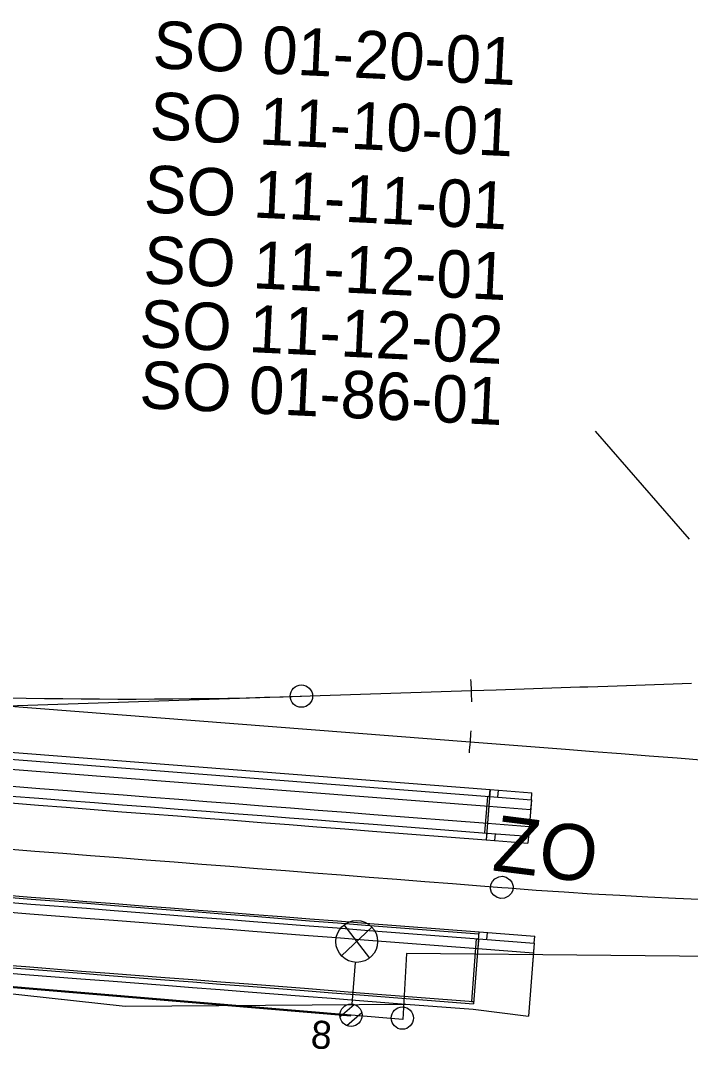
# Model space of a CAD drawing. Extents: x -669628 to -669207, y -977198 to -977075.
# Drawn here: x -669457.17 to -669433.19, y -977154.05 to -977117.21 of the extents above; entities that cross this region are included whole.
import ezdxf

# ---------------------------------------------------------------- set-up
doc = ezdxf.new("R2010")
doc.units = 0
for name, color, linetype in [('_PS_SO_číslo', 7, 'Continuous'), ('SO 01-86-01', 7, 'Continuous'), ('SO 11-10-01', 7, 'Continuous'), ('SO 11-12-01', 7, 'Continuous')]:
    doc.layers.add(name, color=color, linetype=linetype)

# ---------------------------------------------------------------- blocks, each defined once
blk = doc.blocks.new('POINT_DISPLAY')
blk.add_line((0, 0), (0, 0))

msp = doc.modelspace()

# ---------------------------------------------------------------- linework, layer by layer
at = {"layer": '_PS_SO_číslo'}
msp.add_line((-669436.601, -977131.919), (-669433.231, -977135.786), dxfattribs=at)
at = {"layer": 'SO 01-86-01'}
for p, q in [((-669445.341, -977152.857), (-669517.763, -977146.78)), ((-669445.341, -977152.857), (-669517.763, -977146.78)), ((-669443.485, -977152.976), (-669517.763, -977146.78)), ((-669445.675, -977150.701), (-669444.59, -977149.67)), ((-669445.589, -977149.592), (-669444.676, -977150.779)), ((-669443.348, -977150.615), (-669443.485, -977152.976)), ((-669436.037, -977150.686), (-669443.348, -977150.615)), ((-669421.416, -977150.84), (-669436.037, -977150.686)), ((-669445.191, -977150.932), (-669445.307, -977152.427)), ((-669445.732, -977152.875), (-669445.228, -977152.444)), ((-669445.488, -977153.192), (-669444.951, -977152.733))]:
    msp.add_line(p, q, dxfattribs=at)
for centre, radius in [((-669445.133, -977150.185), 0.749), ((-669445.338, -977152.826), 0.4), ((-669443.501, -977152.927), 0.4)]:
    msp.add_circle(centre, radius, dxfattribs=at)
at = {"layer": 'SO 11-10-01'}
for p, q in [((-669468.123, -977140.931), (-669441.067, -977143.037)), ((-669457.632, -977141.747), (-669441.026, -977141.2)), ((-669441.026, -977141.2), (-669440.143, -977141.171)), ((-669440.143, -977141.171), (-669439.143, -977141.138)), ((-669439.143, -977141.138), (-669438.144, -977141.105)), ((-669438.144, -977141.105), (-669437.144, -977141.072)), ((-669437.144, -977141.072), (-669436.855, -977141.062)), ((-669436.855, -977141.062), (-669436.145, -977141.039)), ((-669436.145, -977141.039), (-669435.146, -977141.006)), ((-669435.146, -977141.006), (-669434.146, -977140.973)), ((-669434.146, -977140.973), (-669433.147, -977140.94)), ((-669441.067, -977143.037), (-669437.657, -977143.302)), ((-669437.657, -977143.302), (-669436.66, -977143.38)), ((-669436.66, -977143.38), (-669435.663, -977143.457)), ((-669435.663, -977143.457), (-669434.666, -977143.535)), ((-669434.666, -977143.535), (-669433.669, -977143.613)), ((-669433.669, -977143.613), (-669432.672, -977143.69)), ((-669457.653, -977146.871), (-669456.656, -977146.949)), ((-669456.656, -977146.949), (-669455.659, -977147.026)), ((-669455.659, -977147.026), (-669454.662, -977147.104)), ((-669454.662, -977147.104), (-669453.665, -977147.182)), ((-669453.665, -977147.182), (-669452.668, -977147.259)), ((-669452.668, -977147.259), (-669451.671, -977147.337)), ((-669451.671, -977147.337), (-669450.674, -977147.414)), ((-669450.674, -977147.414), (-669449.677, -977147.492)), ((-669449.677, -977147.492), (-669448.68, -977147.57)), ((-669448.68, -977147.57), (-669447.683, -977147.647)), ((-669447.683, -977147.647), (-669446.686, -977147.725)), ((-669446.686, -977147.725), (-669445.689, -977147.802)), ((-669445.689, -977147.802), (-669444.692, -977147.88)), ((-669444.692, -977147.88), (-669443.695, -977147.958)), ((-669443.695, -977147.958), (-669442.698, -977148.035)), ((-669442.698, -977148.035), (-669441.701, -977148.113)), ((-669441.701, -977148.113), (-669440.704, -977148.191)), ((-669440.704, -977148.191), (-669439.942, -977148.25)), ((-669439.942, -977148.25), (-669439.707, -977148.268)), ((-669439.707, -977148.268), (-669438.71, -977148.342)), ((-669438.71, -977148.342), (-669437.712, -977148.41)), ((-669437.712, -977148.41), (-669436.714, -977148.473)), ((-669436.714, -977148.473), (-669435.716, -977148.531)), ((-669435.716, -977148.531), (-669434.717, -977148.584)), ((-669434.717, -977148.584), (-669433.718, -977148.632)), ((-669433.718, -977148.632), (-669432.879, -977148.667))]:
    msp.add_line(p, q, dxfattribs=at)
msp.add_lwpolyline([(-669439.973, -977148.649), (-669440.104, -977148.612), (-669440.231, -977148.522), (-669440.305, -977148.436), (-669440.347, -977148.299), (-669440.335, -977148.139), (-669440.274, -977148.037), (-669440.186, -977147.937), (-669440.046, -977147.867), (-669439.911, -977147.851), (-669439.781, -977147.888), (-669439.654, -977147.978), (-669439.58, -977148.064), (-669439.537, -977148.201), (-669439.55, -977148.361), (-669439.611, -977148.463), (-669439.699, -977148.563), (-669439.838, -977148.632), (-669439.973, -977148.649)], dxfattribs=at)
msp.add_circle((-669447.114, -977141.4), 0.4, dxfattribs=at)
for centre, radius, start, end in [((-669457.632, -977141.747), 16.616, 0.5101, 3.2688), ((-669453.379, -976951.504), 190, 265.54926, 271.88929), ((-669457.632, -977141.747), 16.616, 354.1699, 356.9286)]:
    msp.add_arc(centre, radius, start, end, dxfattribs=at)
at = {"layer": 'SO 11-12-01'}
for p, q in [((-669470.705, -977142.635), (-669440.379, -977144.996)), ((-669470.686, -977142.386), (-669440.359, -977144.747)), ((-669470.732, -977142.984), (-669440.406, -977145.345)), ((-669457.478, -977144.628), (-669456.481, -977144.706)), ((-669456.481, -977144.706), (-669455.484, -977144.783)), ((-669455.484, -977144.783), (-669454.487, -977144.861)), ((-669454.487, -977144.861), (-669453.49, -977144.938)), ((-669440.359, -977144.747), (-669440.5, -977146.551)), ((-669440.379, -977144.996), (-669440.359, -977144.747)), ((-669440.359, -977144.747), (-669438.864, -977144.863)), ((-669440.079, -977145.019), (-669440.06, -977144.77)), ((-669438.883, -977145.113), (-669438.864, -977144.863)), ((-669457.525, -977145.226), (-669456.528, -977145.304)), ((-669457.505, -977144.977), (-669456.508, -977145.055)), ((-669456.508, -977145.055), (-669455.511, -977145.132)), ((-669455.511, -977145.132), (-669454.514, -977145.21)), ((-669454.514, -977145.21), (-669453.517, -977145.287)), ((-669453.517, -977145.287), (-669452.52, -977145.365)), ((-669453.49, -977144.938), (-669452.493, -977145.016)), ((-669452.493, -977145.016), (-669451.496, -977145.094)), ((-669451.496, -977145.094), (-669450.499, -977145.171)), ((-669450.499, -977145.171), (-669449.502, -977145.249)), ((-669449.502, -977145.249), (-669448.505, -977145.326)), ((-669440.458, -977144.99), (-669440.56, -977146.296)), ((-669440.382, -977145.046), (-669440.437, -977145.744)), ((-669440.379, -977144.996), (-669438.883, -977145.113)), ((-669438.883, -977145.113), (-669438.985, -977146.419)), ((-669438.883, -977145.113), (-669438.91, -977145.461)), ((-669456.528, -977145.304), (-669455.531, -977145.381)), ((-669455.531, -977145.381), (-669454.534, -977145.459)), ((-669454.534, -977145.459), (-669453.537, -977145.537)), ((-669453.537, -977145.537), (-669452.54, -977145.614)), ((-669452.54, -977145.614), (-669451.543, -977145.692)), ((-669452.52, -977145.365), (-669451.523, -977145.443)), ((-669451.523, -977145.443), (-669450.526, -977145.52)), ((-669450.526, -977145.52), (-669449.529, -977145.598)), ((-669449.529, -977145.598), (-669448.532, -977145.675)), ((-669448.505, -977145.326), (-669447.508, -977145.404)), ((-669447.508, -977145.404), (-669446.511, -977145.482)), ((-669446.511, -977145.482), (-669445.514, -977145.559)), ((-669445.514, -977145.559), (-669444.517, -977145.637)), ((-669444.517, -977145.637), (-669440.453, -977145.953)), ((-669440.406, -977145.345), (-669438.91, -977145.461)), ((-669451.543, -977145.692), (-669450.546, -977145.769)), ((-669450.546, -977145.769), (-669449.549, -977145.847)), ((-669449.549, -977145.847), (-669448.552, -977145.925)), ((-669448.552, -977145.925), (-669447.555, -977146.002)), ((-669448.532, -977145.675), (-669447.535, -977145.753)), ((-669447.555, -977146.002), (-669446.558, -977146.08)), ((-669447.535, -977145.753), (-669446.538, -977145.831)), ((-669446.538, -977145.831), (-669445.541, -977145.908)), ((-669445.541, -977145.908), (-669444.544, -977145.986)), ((-669444.544, -977145.986), (-669440.48, -977146.302)), ((-669440.454, -977145.953), (-669438.957, -977146.066)), ((-669446.558, -977146.08), (-669445.561, -977146.157)), ((-669445.561, -977146.157), (-669444.564, -977146.235)), ((-669444.564, -977146.235), (-669440.5, -977146.551)), ((-669440.481, -977146.302), (-669440.5, -977146.551)), ((-669440.481, -977146.302), (-669438.985, -977146.415)), ((-669440.182, -977146.325), (-669440.2, -977146.574)), ((-669438.985, -977146.415), (-669438.959, -977146.066)), ((-669440.5, -977146.551), (-669439.004, -977146.664)), ((-669438.985, -977146.415), (-669439.004, -977146.664)), ((-669457.786, -977148.586), (-669456.789, -977148.664)), ((-669457.781, -977148.516), (-669456.784, -977148.594)), ((-669456.784, -977148.594), (-669455.787, -977148.671)), ((-669457.8, -977148.765), (-669456.803, -977148.843)), ((-669456.803, -977148.843), (-669454.809, -977148.998)), ((-669456.789, -977148.664), (-669454.795, -977148.819)), ((-669455.787, -977148.671), (-669454.79, -977148.749)), ((-669454.795, -977148.819), (-669453.798, -977148.896)), ((-669454.79, -977148.749), (-669453.793, -977148.827)), ((-669453.798, -977148.896), (-669451.804, -977149.052)), ((-669453.793, -977148.827), (-669452.796, -977148.904)), ((-669452.796, -977148.904), (-669451.799, -977148.982)), ((-669457.827, -977149.114), (-669456.83, -977149.192)), ((-669456.83, -977149.192), (-669454.836, -977149.347)), ((-669454.809, -977148.998), (-669453.812, -977149.076)), ((-669453.812, -977149.076), (-669451.818, -977149.231)), ((-669451.818, -977149.231), (-669450.821, -977149.309)), ((-669451.804, -977149.052), (-669450.807, -977149.129)), ((-669451.799, -977148.982), (-669450.802, -977149.059)), ((-669450.821, -977149.309), (-669449.824, -977149.386)), ((-669450.807, -977149.129), (-669449.81, -977149.207)), ((-669450.802, -977149.059), (-669449.805, -977149.137)), ((-669449.81, -977149.207), (-669448.813, -977149.284)), ((-669449.805, -977149.137), (-669448.808, -977149.215)), ((-669448.813, -977149.284), (-669446.819, -977149.44)), ((-669448.808, -977149.215), (-669447.811, -977149.292)), ((-669447.811, -977149.292), (-669446.814, -977149.37)), ((-669454.836, -977149.347), (-669453.839, -977149.425)), ((-669453.839, -977149.425), (-669451.845, -977149.58)), ((-669451.845, -977149.58), (-669450.848, -977149.658)), ((-669450.848, -977149.658), (-669449.851, -977149.735)), ((-669449.824, -977149.386), (-669448.827, -977149.464)), ((-669448.827, -977149.464), (-669446.833, -977149.619)), ((-669446.833, -977149.619), (-669445.836, -977149.697)), ((-669446.819, -977149.44), (-669445.822, -977149.517)), ((-669446.814, -977149.37), (-669445.817, -977149.448)), ((-669445.836, -977149.697), (-669444.839, -977149.774)), ((-669445.822, -977149.517), (-669444.825, -977149.595)), ((-669445.817, -977149.448), (-669444.82, -977149.525)), ((-669444.825, -977149.595), (-669440.761, -977149.911)), ((-669444.82, -977149.525), (-669440.756, -977149.841)), ((-669449.851, -977149.735), (-669448.854, -977149.813)), ((-669448.854, -977149.813), (-669446.86, -977149.968)), ((-669446.86, -977149.968), (-669445.863, -977150.046)), ((-669445.863, -977150.046), (-669444.866, -977150.123)), ((-669444.839, -977149.774), (-669440.775, -977150.091)), ((-669440.779, -977150.141), (-669440.756, -977149.841)), ((-669440.756, -977149.841), (-669438.762, -977149.997)), ((-669440.476, -977150.114), (-669440.457, -977149.865)), ((-669438.781, -977150.246), (-669438.762, -977149.997)), ((-669444.866, -977150.123), (-669440.802, -977150.44)), ((-669440.855, -977150.085), (-669441.029, -977152.328)), ((-669440.775, -977150.091), (-669440.956, -977152.414)), ((-669440.855, -977150.085), (-669440.775, -977150.091)), ((-669440.779, -977150.141), (-669440.802, -977150.44)), ((-669440.802, -977150.44), (-669438.808, -977150.595)), ((-669440.775, -977150.091), (-669438.781, -977150.246)), ((-669438.781, -977150.246), (-669438.985, -977152.863)), ((-669438.781, -977150.246), (-669438.839, -977150.994)), ((-669469.174, -977150.785), (-669453.419, -977152.5)), ((-669457.981, -977151.088), (-669456.984, -977151.166)), ((-669457.975, -977151.009), (-669456.978, -977151.086)), ((-669456.984, -977151.166), (-669454.99, -977151.321)), ((-669456.978, -977151.086), (-669454.984, -977151.242)), ((-669457.996, -977151.288), (-669456.999, -977151.365)), ((-669457.996, -977151.288), (-669456.999, -977151.365)), ((-669456.999, -977151.365), (-669455.005, -977151.521)), ((-669456.999, -977151.365), (-669455.005, -977151.521)), ((-669455.005, -977151.521), (-669454.008, -977151.598)), ((-669455.005, -977151.521), (-669454.008, -977151.598)), ((-669454.99, -977151.321), (-669453.993, -977151.399)), ((-669454.984, -977151.242), (-669453.987, -977151.319)), ((-669453.993, -977151.399), (-669451.999, -977151.554)), ((-669453.987, -977151.319), (-669451.993, -977151.474)), ((-669451.993, -977151.474), (-669450.996, -977151.552)), ((-669454.008, -977151.598), (-669452.014, -977151.753)), ((-669454.008, -977151.598), (-669452.014, -977151.753)), ((-669452.014, -977151.753), (-669451.017, -977151.831)), ((-669452.014, -977151.753), (-669451.017, -977151.831)), ((-669451.999, -977151.554), (-669451.002, -977151.632)), ((-669451.017, -977151.831), (-669450.02, -977151.909)), ((-669451.017, -977151.831), (-669450.02, -977151.909)), ((-669451.002, -977151.632), (-669450.005, -977151.709)), ((-669450.996, -977151.552), (-669449.999, -977151.63)), ((-669450.02, -977151.909), (-669449.024, -977151.986)), ((-669450.02, -977151.909), (-669449.024, -977151.986)), ((-669450.005, -977151.709), (-669449.008, -977151.787)), ((-669449.999, -977151.63), (-669449.002, -977151.707)), ((-669449.008, -977151.787), (-669447.014, -977151.942)), ((-669449.002, -977151.707), (-669447.008, -977151.862)), ((-669447.008, -977151.862), (-669446.011, -977151.94)), ((-669449.024, -977151.986), (-669447.03, -977152.142)), ((-669449.024, -977151.986), (-669447.03, -977152.142)), ((-669447.03, -977152.142), (-669446.033, -977152.219)), ((-669447.03, -977152.142), (-669446.033, -977152.219)), ((-669447.014, -977151.942), (-669446.017, -977152.02)), ((-669446.033, -977152.219), (-669445.036, -977152.297)), ((-669446.033, -977152.219), (-669445.036, -977152.297)), ((-669446.017, -977152.02), (-669445.02, -977152.097)), ((-669446.011, -977151.94), (-669445.014, -977152.018)), ((-669445.02, -977152.097), (-669440.956, -977152.414)), ((-669445.014, -977152.018), (-669440.95, -977152.334)), ((-669453.419, -977152.5), (-669443.371, -977152.426)), ((-669445.036, -977152.297), (-669443.371, -977152.426)), ((-669445.036, -977152.297), (-669443.371, -977152.426)), ((-669443.371, -977152.426), (-669440.971, -977152.613)), ((-669441.029, -977152.328), (-669440.95, -977152.334)), ((-669440.971, -977152.613), (-669438.985, -977152.863))]:
    msp.add_line(p, q, dxfattribs=at)

# ---------------------------------------------------------------- block references
at = {"layer": 'SO 01-86-01', "rotation": -4.450857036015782}
msp.add_blockref('POINT_DISPLAY', (-669445.338, -977152.826), dxfattribs=at)
at = {"layer": 'SO 11-10-01'}
msp.add_blockref('POINT_DISPLAY', (-669447.114, -977141.4), dxfattribs=at)

# ---------------------------------------------------------------- texts
at = {"layer": '_PS_SO_číslo'}
for s, p in [('SO 01-20-01', (-669452.461, -977118.913)), ('SO 11-10-01', (-669452.567, -977121.462)), ('SO 11-11-01', (-669452.775, -977124.077)), ('SO 11-12-01', (-669452.791, -977126.61)), ('SO 11-12-02', (-669452.932, -977128.896)), ('SO 01-86-01', (-669452.935, -977131.084))]:
    msp.add_text(s, height=1.7, rotation=357.3, dxfattribs=at).set_placement(p)
at = {"layer": 'SO 01-86-01'}
msp.add_text('8', height=1, rotation=356.1, dxfattribs=at).set_placement((-669446.8, -977154))
at = {"layer": 'SO 11-10-01'}
msp.add_text('ZO', height=2, rotation=352.8068, dxfattribs=at).set_placement((-669440.322, -977147.637))

doc.saveas('drawing.dxf')
